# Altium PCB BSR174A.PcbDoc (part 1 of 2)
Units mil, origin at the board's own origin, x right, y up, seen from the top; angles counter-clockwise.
Board outline 4000 x 3000 mil, 6 copper layers (Top Layer, Signal Layer 1, Signal Layer 2, Signal Layer 3, Signal Layer 4, Bottom Layer), stack 61.8 mil thick; 80 components, 28 nets, 166 pads, 381 vias.
Unrouted connection lines stored in the file: 48.
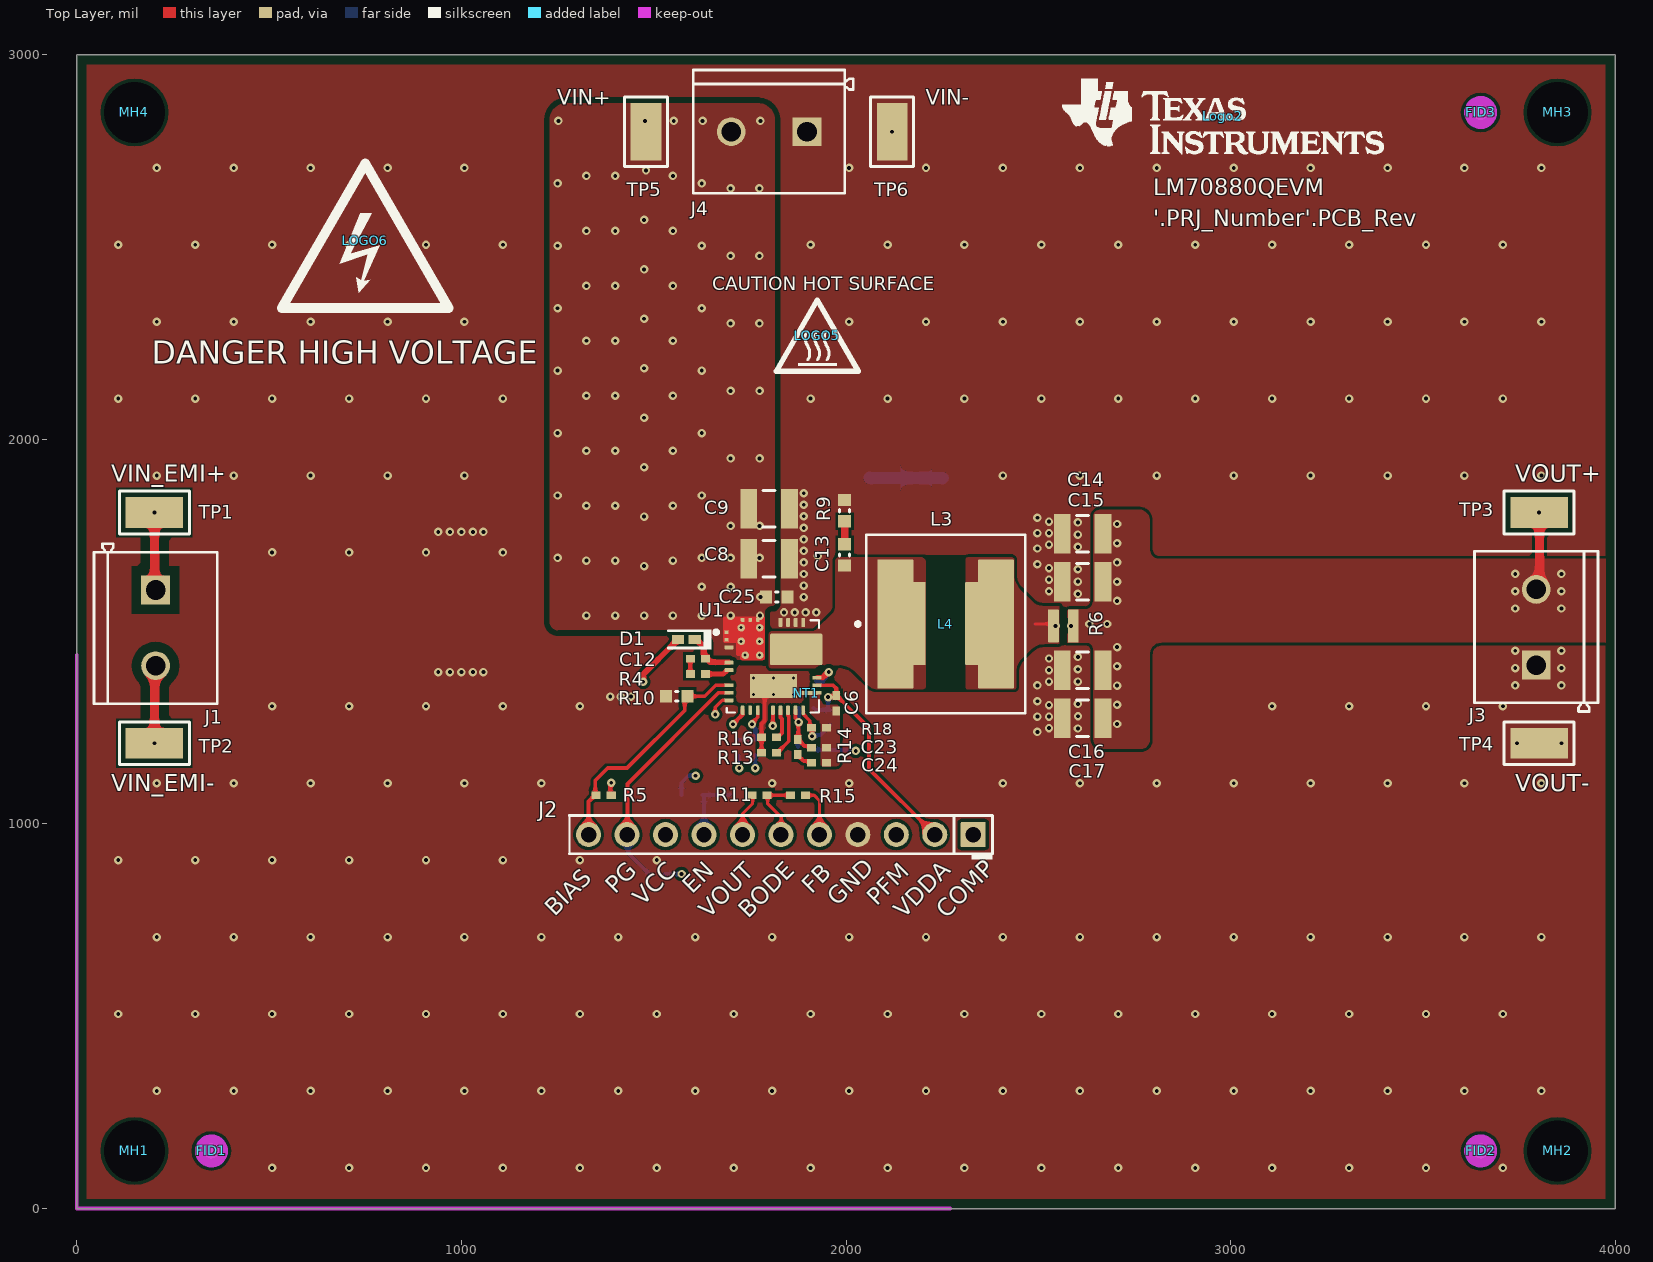
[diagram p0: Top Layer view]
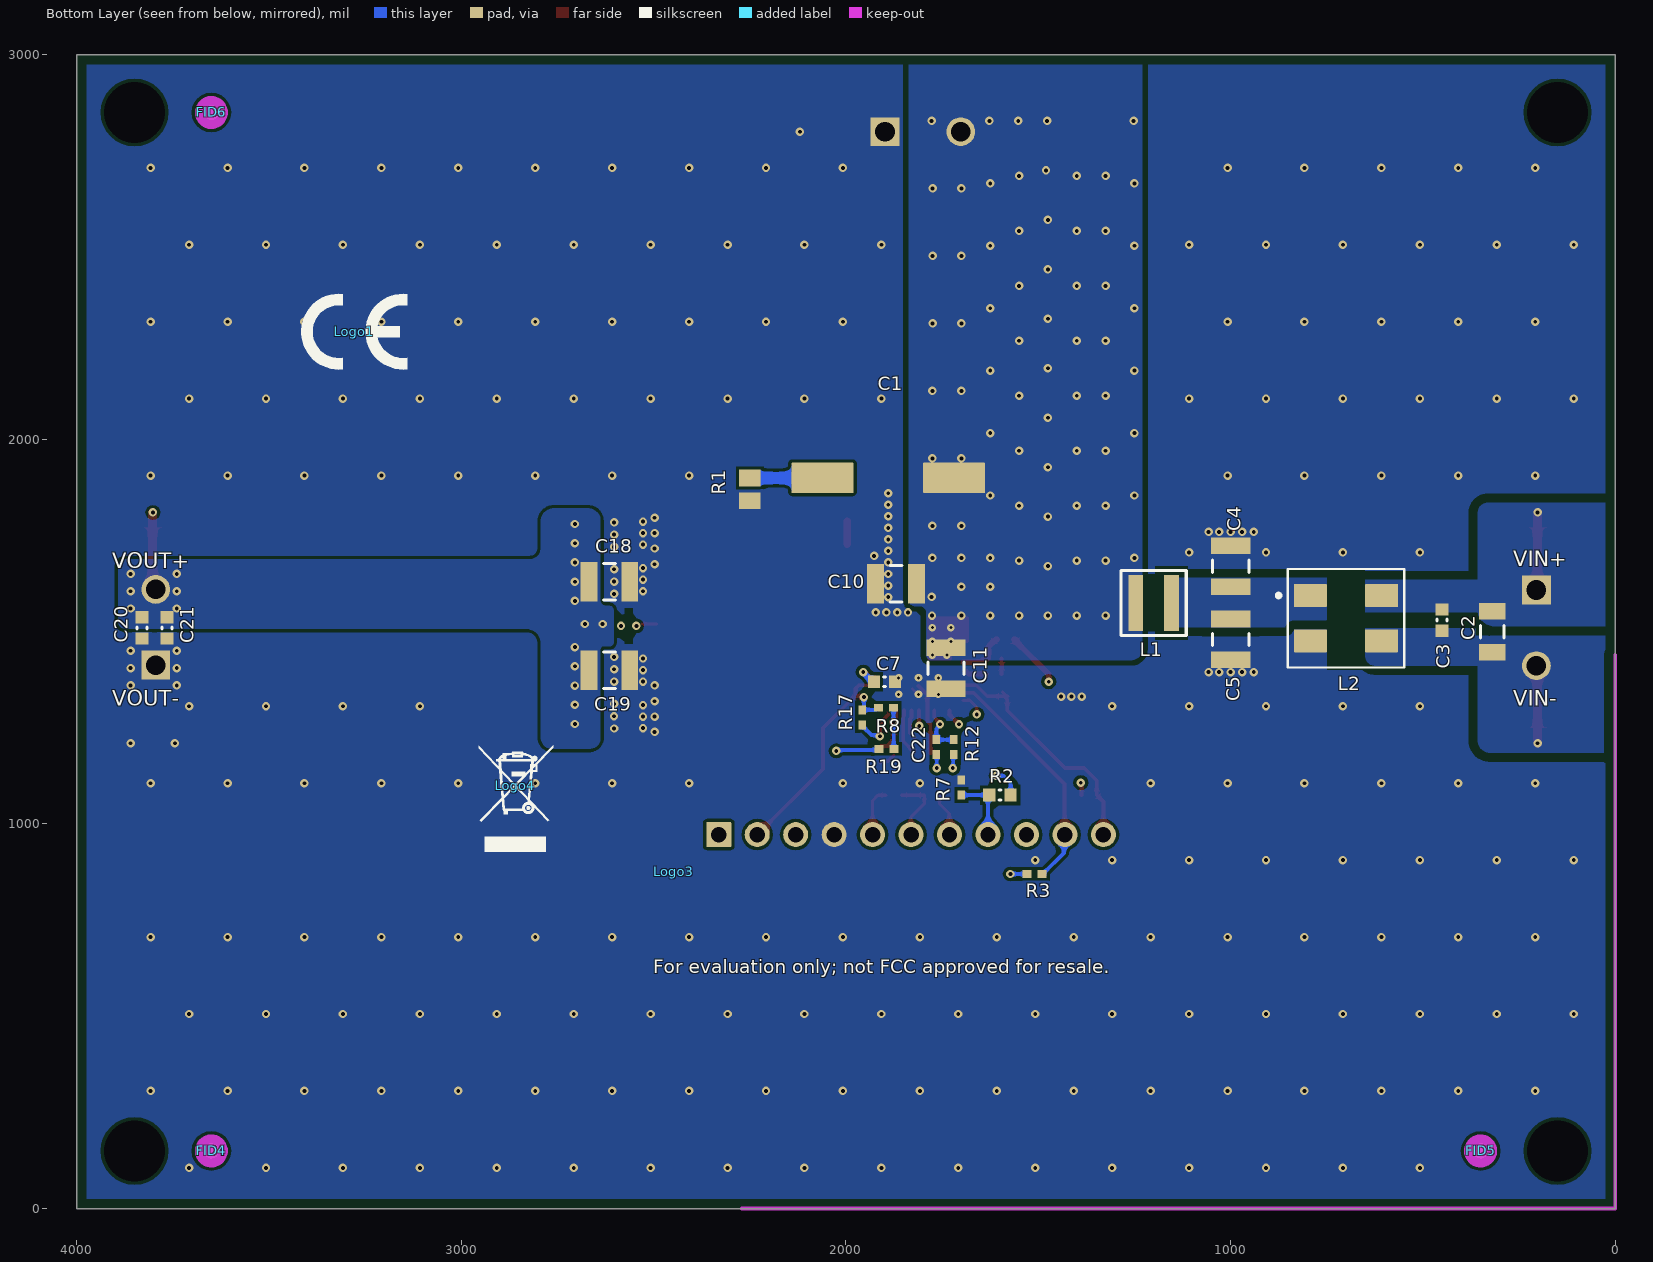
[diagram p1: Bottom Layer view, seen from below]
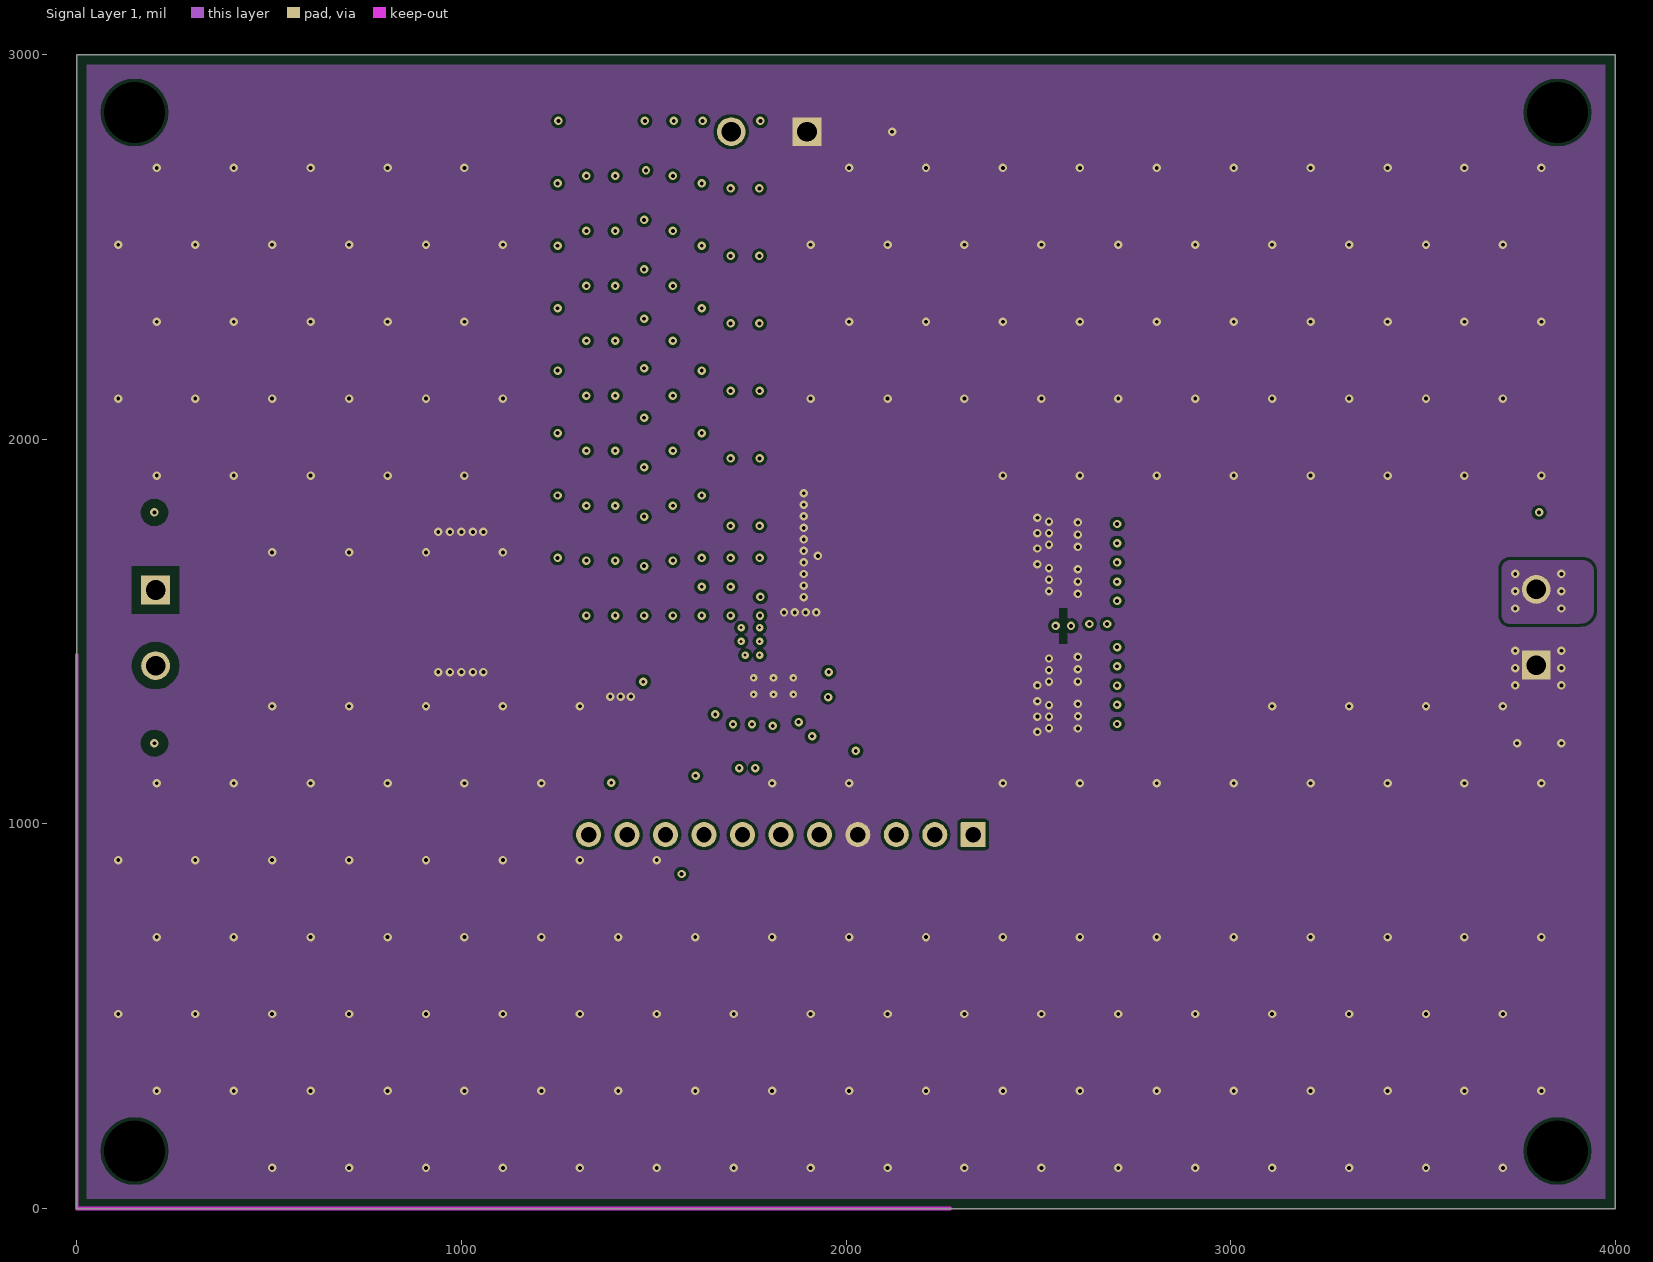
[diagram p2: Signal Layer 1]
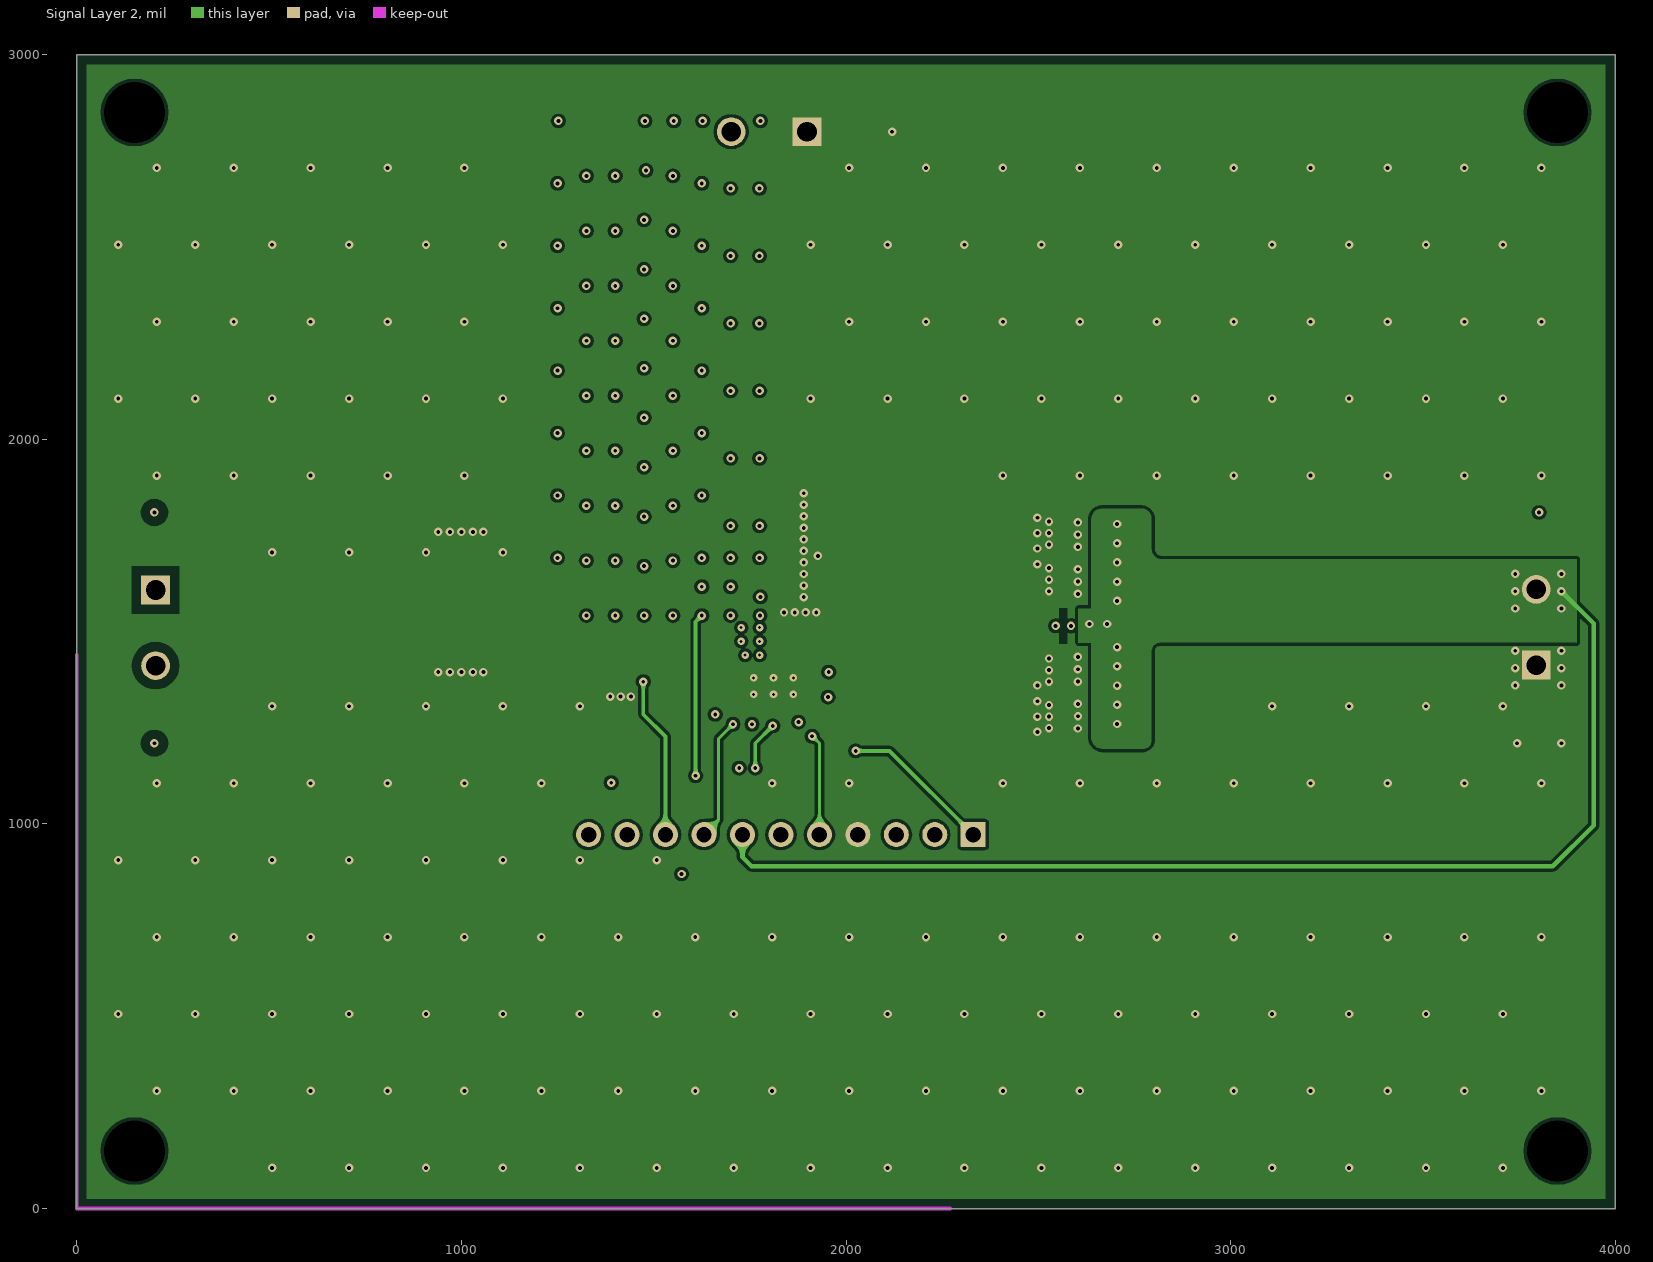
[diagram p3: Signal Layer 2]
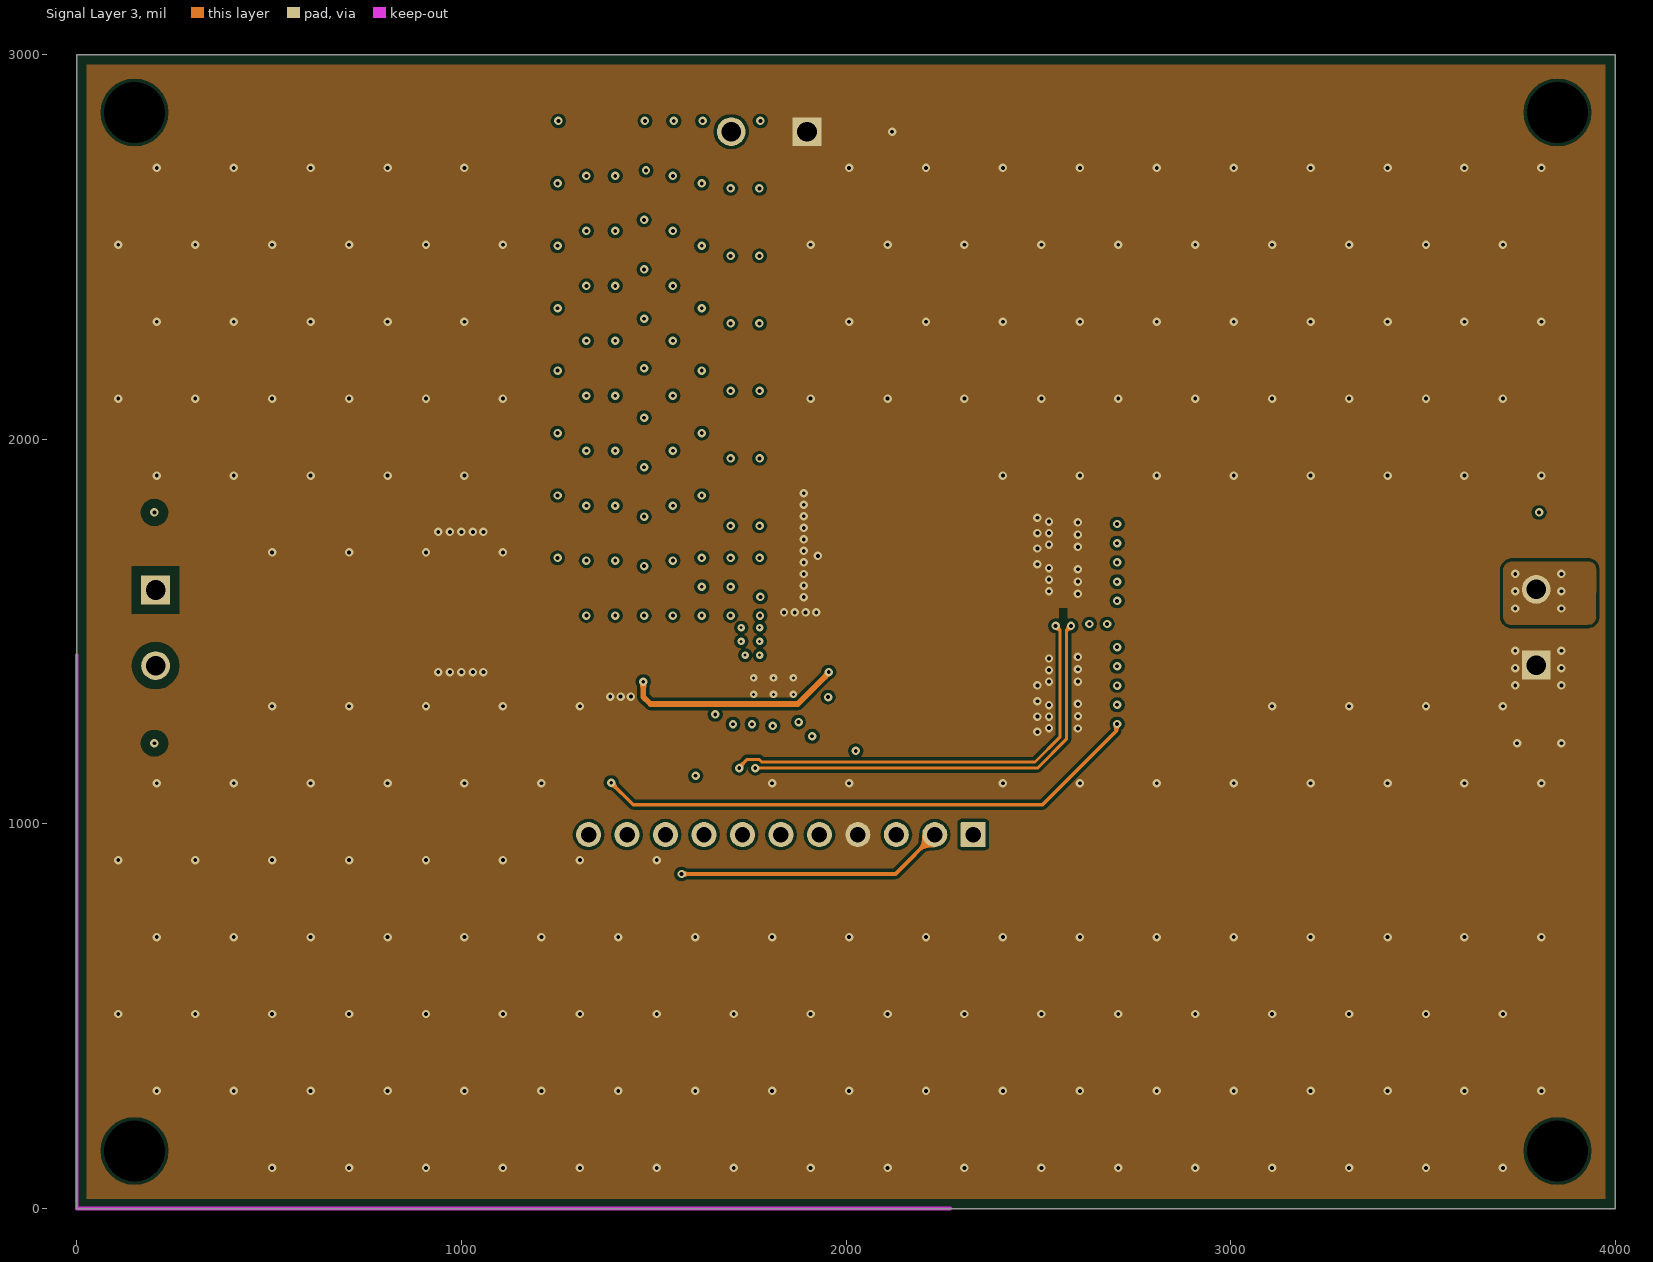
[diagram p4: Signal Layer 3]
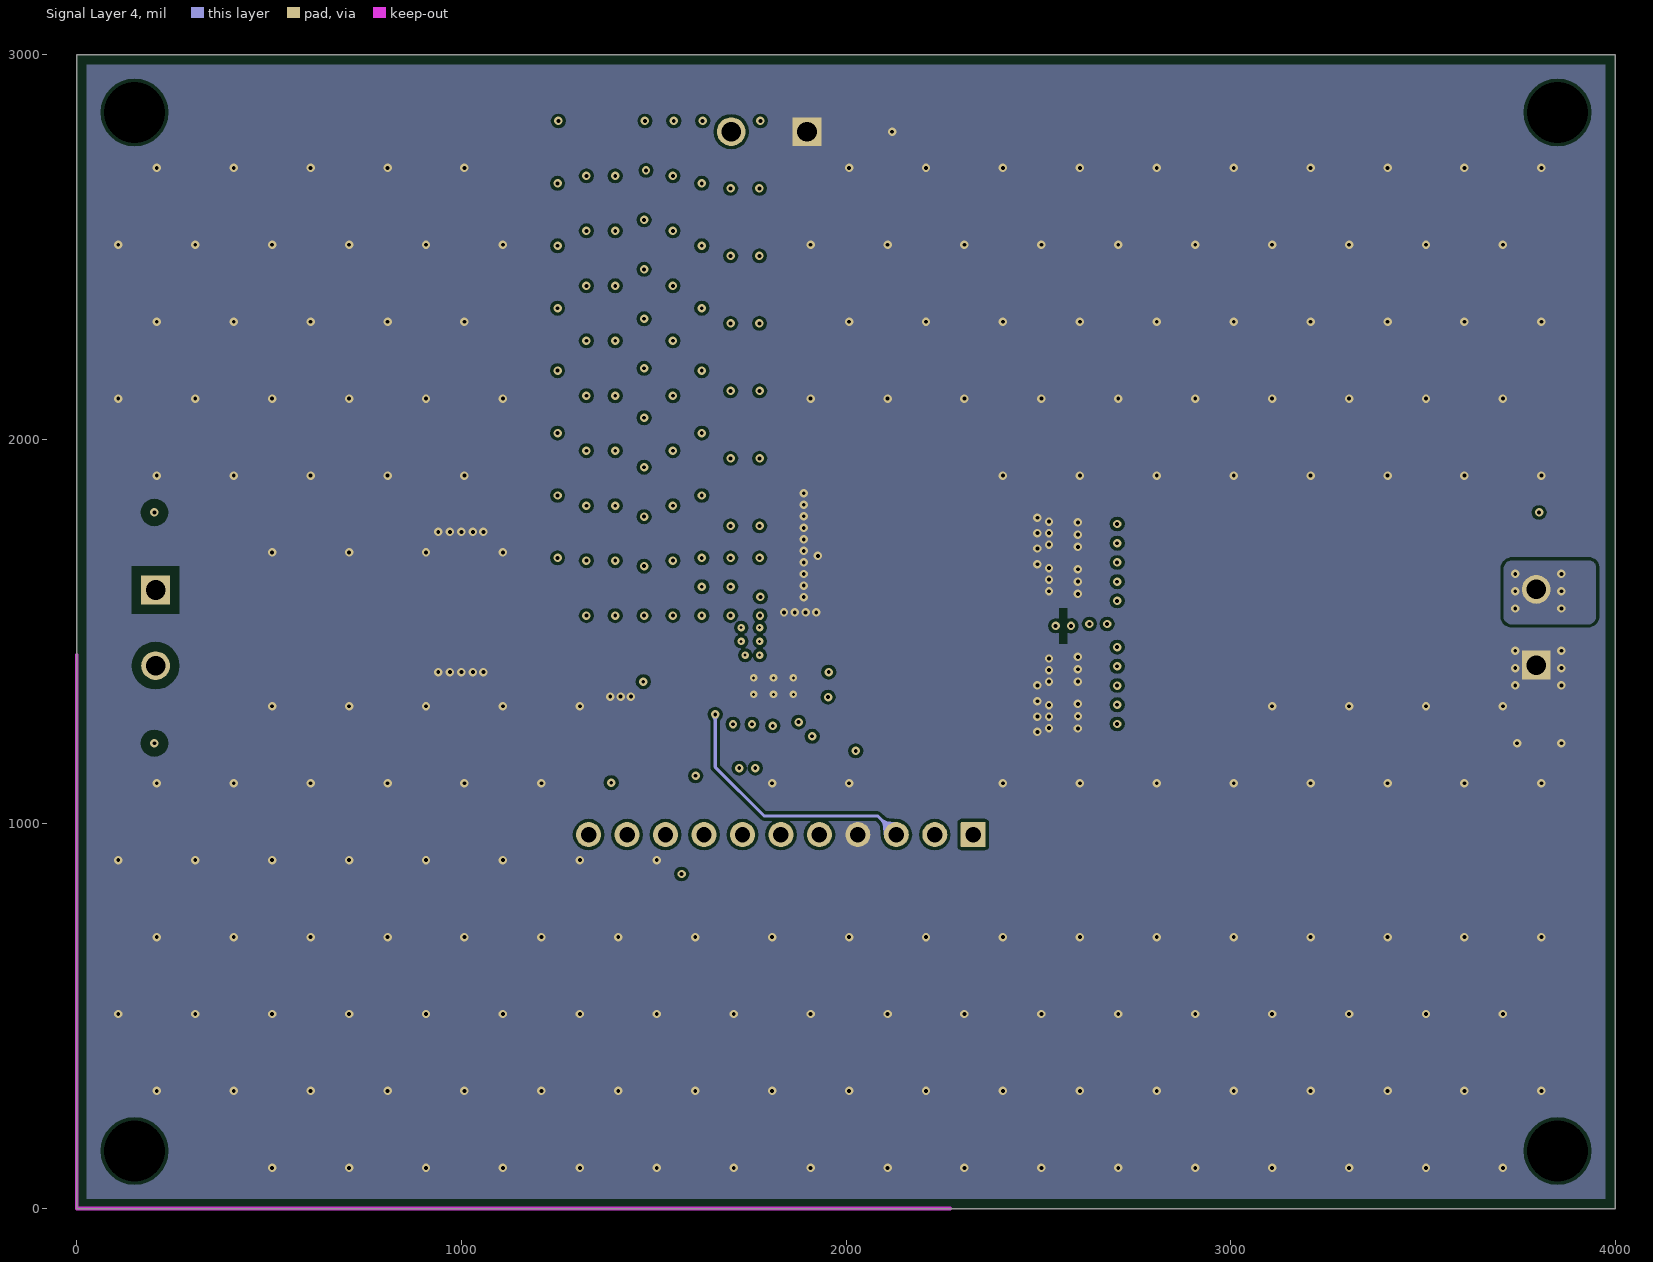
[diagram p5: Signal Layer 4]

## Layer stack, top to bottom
Top Solder: solder mask 0.4, Solder Resist, Dk 3.5
Top Layer: signal copper 2.8
Dielectric1: core 9, FR4 Hi Tg, Dk 4.8
Signal Layer 1: signal copper 2.8
Dielectric 2: prepreg 9, FR4 Hi Tg, Dk 4.2
Signal Layer 2: signal copper 2.8
Dielectric 3: core 9, FR4 Hi Tg, Dk 4.2
Signal Layer 3: signal copper 2.8
Dielectric 4: prepreg 9, FR4 Hi Tg, Dk 4.2
Signal Layer 4: signal copper 2.8
Dielectric 5: core 9, FR4 Hi Tg, Dk 4.2
Bottom Layer: signal copper 2.8
Bottom Solder: solder mask 0.4, Solder Resist, Dk 3.5

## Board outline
0,0 0,3000 4000,3000 4000,0

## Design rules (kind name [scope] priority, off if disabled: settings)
AcuteAngle [All] p1: minimum=4.50000000000000E+0001 checktracksonly=FALSE
AssemblyTestPointUsage [All] p1: valid=2
BoardOutlineClearance BoardOutlineClearance_MountingHoles [OnCopper and InComponentClass('Mounting Holes')] p1: gap=39.37 ignorepadtopadclearanceinfootprint=FALSE
BoardOutlineClearance BoardOutlineClearance_Poly [OnCopper and IsPoly] p2: gap=25 ignorepadtopadclearanceinfootprint=FALSE
BoardOutlineClearance [OnCopper and Not InComponentClass('Logo') and not InComponentClass('FiducialMark') and not InRegion(1000,500,4000,800) and not InPoly] p3: gap=50 ignorepadtopadclearanceinfootprint=FALSE
Clearance "Schematic Clearance Constraint" [InNet('NetC4_1')] p1: gap=24 ignorepadtopadclearanceinfootprint=TRUE
Clearance Clearance_5 [(InNet('NetC4_1') AND OnLayer('Bottom Layer')) vs InNet('VIN') And OnLayer('Bottom Layer')] p2: gap=15 ignorepadtopadclearanceinfootprint=FALSE
Clearance Clearance_4 [(InNet('NetC4_1') AND OnLayer('Bottom Layer')) vs InNet('GND') And OnLayer('Bottom Layer')] p3: gap=15 ignorepadtopadclearanceinfootprint=FALSE
Clearance Clearance_3 [(InNet('NetC5_1') AND OnLayer('Bottom Layer')) vs InNet('GND') And OnLayer('Bottom Layer')] p4: gap=15 ignorepadtopadclearanceinfootprint=FALSE
Clearance "SW and GND top" [(InNet('SW') AND OnLayer('Top Layer')) vs InNet('GND') And OnLayer('Top Layer')] p5: gap=8 ignorepadtopadclearanceinfootprint=FALSE
Clearance "Vin and GND top" [(InNet('VIN') AND OnLayer('Top Layer')) vs InNet('GND') And OnLayer('Top Layer')] p6: gap=15 ignorepadtopadclearanceinfootprint=FALSE
Clearance "Vin and GND layer2" [(InNet('VIN') AND OnLayer('Signal Layer 1')) vs InNet('GND') And OnLayer('Signal Layer 1')] p7: gap=8 ignorepadtopadclearanceinfootprint=FALSE
Clearance "SW to GND bottom" [(InNet('SW') AND OnLayer('Bottom Layer')) vs InNet('GND') And OnLayer('Bottom Layer')] p8: gap=8 ignorepadtopadclearanceinfootprint=FALSE
Clearance "Vin to GND bottom" [(InNet('VIN') AND OnLayer('Bottom Layer')) vs InNet('GND') And OnLayer('Bottom Layer')] p9: gap=10 ignorepadtopadclearanceinfootprint=FALSE except(15: Fill-Fill Fill-Poly Fill-Region Poly-Poly Poly-Region Region-Region)
Clearance Clearance_2 [InNamedPolygon('TOP_LAYER_SW_P2403')] p10: gap=40 ignorepadtopadclearanceinfootprint=FALSE
Clearance Clearance_1 [InNamedPolygon('TOP_LAYER_SW_P2403')] p11: gap=10 ignorepadtopadclearanceinfootprint=FALSE except(0: Arc-Hole Track-Hole SMDPad-Hole THPad-Hole Via-Hole Fill-Hole Poly-Hole Region-Hole Text-Hole)
Clearance "Schematic Clearance Constraint_2" [InNet('NetC2_1')] p12: gap=24 ignorepadtopadclearanceinfootprint=TRUE
Clearance "Schematic Clearance Constraint_1" [InNet('EMIGND')] p13: gap=24 ignorepadtopadclearanceinfootprint=FALSE
Clearance Clearance_Keepouts [((IsTrack Or IsArc) And Not InPoly) And IsFree and IsKeepOut vs ((IsTrack Or IsArc) And Not InPoly) And IsFree and IsKeepOut] p14: gap=10 ignorepadtopadclearanceinfootprint=FALSE
Clearance Clearance_VIN [(InPolygon AND InNet('GND'))] p15: gap=8 ignorepadtopadclearanceinfootprint=TRUE
Clearance Clearance_Poly [InPolygon] p16: gap=10 ignorepadtopadclearanceinfootprint=TRUE except(8: Arc-SMDPad Track-SMDPad SMDPad-SMDPad)
Clearance Clearance_FiducialMark [IsKeepOut and InComponentClass('FiducialMark') vs IsPad and InComponentClass('FiducialMark')] p17: gap=0 ignorepadtopadclearanceinfootprint=FALSE
Clearance [All] p18: gap=7.87 ignorepadtopadclearanceinfootprint=TRUE
ComponentClearance J1 [InComponent('J1') vs InComponent('C5')] p1: gap=0 collisioncheckmode=3 verticalgap=0 showdistances=FALSE
ComponentClearance J3 [InComponent('J3') vs InComponent('C33')] p2: gap=0 collisioncheckmode=3 verticalgap=0 showdistances=FALSE
ComponentClearance ComponentClearance_NetTie [(HasFootprint('Net-Tie_10mil') OR HasFootprint('Net-Tie_10milWide_30milLong'))] p3: gap=0 collisioncheckmode=3 verticalgap=0 showdistances=FALSE
ComponentClearance ComponentClearance_MountingHoles_FiducialMarks [InComponentClass('Mounting Holes') vs InComponentClass('FiducialMark')] p4: gap=50 collisioncheckmode=3 verticalgap=10 showdistances=FALSE
ComponentClearance ComponentClearance_Shunt [InComponentClass('Header') vs InComponentClass('Shunt')] p5: gap=0 collisioncheckmode=3 verticalgap=0 showdistances=FALSE
ComponentClearance ComponentClearance_Logo [InComponentClass('Logo')] p6: gap=50 collisioncheckmode=3 verticalgap=10 showdistances=FALSE
ComponentClearance ComponentClearance_ScrewToNut [(HasFootprint('NY PMS 440 0025 PH')) vs (HasFootprint('Keystone_1902C'))] p7: gap=5 collisioncheckmode=3 verticalgap=10 showdistances=FALSE
ComponentClearance ComponentClearance_MountingHoles [InComponentClass('Mounting Holes')] p8: gap=90 collisioncheckmode=3 verticalgap=100 showdistances=FALSE
ComponentClearance ComponentClearance_SmallPassives [HasFootprint('0201*') or HasFootprint('0402*') or HasFootprint('0508') or HasFootprint('0603*') or HasFootprint('0612') or HasFootprint('0805*') or HasFootprint('0815*') or HasFootprint('0830*') or HasFootprint('1206*') or HasFootprint('1210*') or HasFootprint('1808*') or HasFootprint('1812*') or HasFootprint('1825*') or HasFootprint('2010*') or HasFootprint('2220*') or HasFootprint('2225*') or HasFootprint('2512*') or HasFootprint('2728*') or HasFootprint('3518*') vs HasFootprint('0201*') or HasFootprint('0402*') or HasFootprint('0508') or HasFootprint('0603*') or HasFootprint('0612') or HasFootprint('0805*') or HasFootprint('0815*') or HasFootprint('0830*') or HasFootprint('1206*') or HasFootprint('1210*') or HasFootprint('1808*') or HasFootprint('1812*') or HasFootprint('1825*') or HasFootprint('2010*') or HasFootprint('2220*') or HasFootprint('2225*') or HasFootprint('2512*') or HasFootprint('2728*') or HasFootprint('3518*')] p9: gap=14.96 collisioncheckmode=3 verticalgap=10 showdistances=FALSE
ComponentClearance ComponentClearance_THtoSMT [IsThruComponent vs IsSMTComponent] p10: gap=40 collisioncheckmode=3 verticalgap=30 showdistances=FALSE
ComponentClearance ComponentClearance_THtoTH [IsThruComponent vs IsThruComponent] p11: gap=30 collisioncheckmode=3 verticalgap=30 showdistances=FALSE
ComponentClearance "Clearance L3" [InComponent('L4') vs InComponent('L3')] p12: gap=0 collisioncheckmode=3 verticalgap=0 showdistances=FALSE
ComponentClearance [All] p13: gap=15 collisioncheckmode=3 verticalgap=2 showdistances=FALSE
DiffPairsRouting [All] p1: maxlimit=100 minlimit=10 mostfreqgap=10 toplayer_minwidth=15 toplayer_maxwidth=15 toplayer_prefwidth=15 midlayer1_minwidth=15 midlayer1_maxwidth=15 midlayer1_prefwidth=15 midlayer2_minwidth=15 midlayer2_maxwidth=15 midlayer2_prefwidth=15 midlayer3_minwidth=15 midlayer3_maxwidth=15 midlayer3_prefwidth=15 midlayer4_minwidth=15 midlayer4_maxwidth=15 midlayer4_prefwidth=15 bottomlayer_minwidth=15 bottomlayer_maxwidth=15 bottomlayer_prefwidth=15 maxuncoupledlength=1000
FabricationTestPointUsage TestPointUsage [All] p1: valid=2 allowmultiple=FALSE
FabricationTestpoint Testpoint [All] p1: side=3 testpointundercomponent=TRUE minsize=40 maxsize=100 preferedsize=60 minholesize=0 maxholesize=40 preferedholesize=32 testpointgrid=1 allowsidetop=TRUE allowsidebottom=TRUE usegrid=TRUE gridtolerance=0.01
FanoutControl Fanout_LCC [IsLCC] p1: bgadir=Out bgaviamode=Centered fanoutstyle=Auto fanoutdirection=Alternating viagrid=1 // Fanout_LCC (Default Rule)
FanoutControl Fanout_BGA [IsBGA] p2: bgadir=Out bgaviamode=Centered fanoutstyle=Auto fanoutdirection=Alternating viagrid=1 // Fanout_BGA (Default Rule)
FanoutControl Fanout_Default [All] p4: bgadir=Out bgaviamode=Centered fanoutstyle=Auto fanoutdirection=Alternating viagrid=1 // Fanout_Default (Default Rule)
FanoutControl Fanout_Small [(CompPinCount < 5)] p5: bgadir=Out bgaviamode=Centered fanoutstyle=Auto fanoutdirection=OutThenIn viagrid=1 // Fanout_Small (Default Rule)
HoleSize [All] p1: absolutevalues=TRUE maxlimit=251 minlimit=7.87 maxpercent=80.000 minpercent=20.000
MinimumAnnularRing MinimumAnnularRing_ThermalPadVias [IsVia and InAnyComponent] p1: minimumring=5.91
MinimumAnnularRing [All] p2: minimumring=5
MinimumSolderMaskSliver MinimumSolderMaskSliver_Logo [InComponentClass('Logo') vs InComponentClass('Logo')] p1: minsoldermaskwidth=0.7
MinimumSolderMaskSliver [All] p2: minsoldermaskwidth=3.94
PlaneClearance PlaneClearance_1 [InNet('GND') And OnLayer('Signal Layer 1')] p1: clearance=8
PlaneClearance [All] p2: clearance=20
PlaneConnect [All] p1: planeconnectstyle=Relief reliefexpansion=10 reliefentries=4 reliefconductorwidth=10 reliefairgap=10
PolygonConnect [All] p1: connectstyle=Direct reliefconductorwidth=10 reliefentries=4 polygonreliefangle="90 Angle" airgapwidth=10
RoutingVias ThermalPadVias [IsVia and InAnyComponent] p1: holewidth=7.87 width=19.68 viastyle="Through Hole" minholewidth=7.87 minwidth=19.68 maxholewidth=12.99 maxwidth=23.62
RoutingVias [All] p2: holewidth=10 width=22 viastyle="Through Hole" minholewidth=7.87 minwidth=18 maxholewidth=40 maxwidth=65
SilkToBoardRegionClearance [Not ((IsComment or IsDesignator) And (Hide <> 'False')) and not InRegion(1000,500,4000,800)] p1:
SilkToSilkClearance SilkToSilkClearance_Pb-FreeLogo [(HasFootprint('Pb-Free_Overlay_Medium') OR HasFootprint('Pb-Free_Overlay_Small')) vs (HasFootprint('Pb-Free_Overlay_Medium') OR HasFootprint('Pb-Free_Overlay_Small'))] p1: silktosilkclearance=0
SilkToSilkClearance [All] p2: silktosilkclearance=3.94
SilkToSolderMaskClearance SilkToComponentPadClearance [(IsPad or IsFill or IsRegion) and InAnycomponent] p1: minsilkscreentomaskgap=5 clearancetoexposedcopper=TRUE
SilkToSolderMaskClearance "Silk to Solder Mask Opening" [All] p2: minsilkscreentomaskgap=3.94 clearancetoexposedcopper=FALSE
SolderMaskExpansion [All] p1: expansion=1.97 istentingtop=FALSE
UnRoutedNet [All] p1: checkbadconnections=TRUE
Width [All] p1: maxlimit=250 minlimit=8 preferedwidth=10 checkconnectedcopper=TRUE
13 further rules are at their usual default settings.

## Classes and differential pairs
component class BSR174A-Main: C1 C2 C3 C4 C5 C6 C7 C8 C9 C10 C11 C12 C13 C14 C15 C16 C17 C18 C19 C20 C21 C22 C23 C24 C25 D1 J1 J2 J3 J4 L1 L2 L3 L4 NT1 R1 R2 R3 R4 R5 R6 R7 R8 R9 R10 R11 R12 R13 R14 R15 R16 R17 R18 R19 RDC TP1 TP2 TP3 TP4 TP5 TP6 U1
component class Header: J2
component class Logo: Logo2
component class BSR174A-Hardware: FID1 FID2 FID3 FID4 FID5 FID6 H10 Logo1 Logo2 Logo3 Logo4 LOGO5 LOGO6 MH1 MH2 MH3 MH4 ZZ1 ZZ2 ZZ3
component class FiducialMark: FID1 FID2 FID3 FID4 FID5 FID6
component class AssemblyNote: ZZ1 ZZ2 ZZ3

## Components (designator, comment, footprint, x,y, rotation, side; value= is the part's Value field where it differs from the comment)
C1 "EEE-TG2A330P" TG_V_1000x1020 1890,1900 r0 bottom value=33uF
C2 "CGA5L3X7S2A225K160AB" 1206_180L 320,1500 r270 bottom value=2.2uF
C3 "GCJ188R72A104KA01D" 0603L 450,1530 r270 bottom value=0.1uF
C4 "GCM32DC72A475KE02L" 1210_220L 1000,1670 r90 bottom value=4.7uF
C5 "GCM32DC72A475KE02L" 1210_220L 1000,1480 r270 bottom value=4.7uF
C6 "C0402C104K8RACAUTO" 0402L 1975,1314 r90 top value=0.1uF
C7 "GRM188Z71A475ME15D" 0603L 1900,1370 r180 bottom value=4.7uF
C8 "GCM32DC72A475KE02L" 1210_220L 1800,1690 r0 top value=4.7uF
C9 "GCM32DC72A475KE02L" 1210_220L 1800,1820 r0 top value=4.7uF
C10 "GCM32DC72A475KE02L" 1210_220L 1870,1625 r0 bottom value=4.7uF
C11 "GCM32DC72A475KE02L" 1210_220L 1740,1405 r270 bottom value=4.7uF
C12 "GRM155R71E473KA88D" 0402L 1615,1430 r180 top value=0.047uF
C13 "GRM1885C2A101JA01D" 0603L 1996.45,1699.65 r90 top value=100pF
C14 "GRM32ER71A476KE15L" 1210_270L 2615,1755 r180 top value=47uF
C15 "GRM32ER71A476KE15L" 1210_270L 2615,1630 r180 top value=47uF
C16 "GRM32ER71A476KE15L" 1210_270L 2615,1400 r180 top value=47uF
C17 "GRM32ER71A476KE15L" 1210_270L 2615,1275 r180 top value=47uF
C18 "GRM32ER71A476KE15L" 1210_270L 2615,1630 r180 bottom value=47uF
C19 "GRM32ER71A476KE15L" 1210_270L 2615,1400 r180 bottom value=47uF
C20 "CGA3E2X7R1H104K080AA" 0603L 3830,1510 r270 bottom value=0.1uF
C21 "CGA3E2X7R1H104K080AA" 0603L 3765,1510 r270 bottom value=0.1uF
C22 "GCM1555C1H330JA16D" 0402L 1765,1200 r90 bottom value=33pF
C23 "CGA2B2C0G1H470J050BA" 0402L 1930,1198 r0 top value=47pF
C24 "CGA2B2X7R1H682K050BA" 0402L 1930,1159 r0 top value=6800pF
C25 "GCJ188R72A104KA01D" 0603L 1820,1590 r0 top value=0.1uF
D1 "BAT41KFILM" SOD-523 1585,1480 r180 top value=100V
FID1 "Fiducial" Fiducial10-20 350,150 r0 top
FID2 "Fiducial" Fiducial10-20 3650,150 r0 top
FID3 "Fiducial" Fiducial10-20 3650,2850 r0 top
FID4 "Fiducial" Fiducial10-20 3650,150 r90 bottom
FID5 "Fiducial" Fiducial10-20 350,150 r90 bottom
FID6 "Fiducial" Fiducial10-20 3650,2850 r90 bottom
J1 "Header_2x1" Phoenix_1729018 205,1510 r270 top
J2 "TSW-111-07-G-S" TSW-111-07-G-S 1830.81,972.34 r180 top
J3 "Header_2x1" Phoenix_1729018 3794.59,1511.57 r90 top
J4 "1729018" Phoenix_1729018 1800,2800 r180 top
L1 "74438356010" WE-MAPI_4020 1200,1575 r0 bottom value=1uH
L2 "CM7060P701R-10" FP-CM7060P701R-10_SMT_CMC_7MM0_6MM0-MFG 700,1535 r180 bottom
L3 "XGL6060-332MEC" FP-XGL6060-332MEC_SMT_6MM51_6MM71-MFG 2258.47,1521.46 r0 top value=3.3uH
L4 "XGL1060-332MEC" FP-XGL1060-332MEC_SMT2_10MM0_11MM3-MFG 2259.09,1519.94 r0 top value=3.3uH
Logo1 "CE Mark" CE_Mark_5mm 3278.8,2280 r180 bottom
Logo2 "Texas Instruments" TI_Stacked_Overlay_Small 2980,2840 r0 top
Logo3 "FCC disclaimer" FCC_disclaimer 2447.81,875.34 r180 bottom
Logo4 "WEEE logo" WEEE_Minimum 2860,1100 r180 bottom
LOGO5 "CAUTION HOT SURFACE" IEC_HotSurface_Small 1925.37,2270.02 r0 top
LOGO6 "DANGER HIGH VOLTAGE" IEC_HighVoltage_Medium 750,2517.01 r0 top
MH1 "MTG_NoPads" MTG_159mil 150,150 r0 top
MH2 "MTG_NoPads" MTG_159mil 3850,150 r0 top
MH3 "MTG_NoPads" MTG_159mil 3850,2850 r0 top
MH4 "MTG_NoPads" MTG_159mil 150,2850 r0 top
NT1 "Net-Tie" Net-Tie_10milWide_30milLong 1896.25,1340.32 r0 top net-tie
R1 "ERJ-6GEY0R00V" 0805L 2250,1870 r90 bottom value=0
R2 "CRCW0603100KFKEA" 0603L 1600,1075 r180 bottom value=100k
R3 "RMCF0402FT100K" 0402L 1510,870 r0 bottom value=100k
R4 "CRCW04020000Z0EDHP" 0402L 1615,1390 r180 top value=0
R5 "CRCW04020000Z0EDHP" 0402L 1370,1075 r180 top value=0
R6 "KRL2012E-M-R005-F-T5" FP-KRL2012E-M-R005-F-T5_0805_WIDE-MFG 2565,1515 r0 top value=5m
R7 "CRCW040219K1FKED" 0402L 1700,1095 r270 bottom value=19.1k
R8 "RMCF0402FT100K" 0402L 1896.26,1301.73 r0 bottom value=100k
R9 "CRCW06032R00FKEA" 0603L 1996.45,1814.68 r90 top value=2.00
R10 "CRCW06030000Z0EA" 0603L 1560,1332.13 r0 top value=0
R11 "CRCW040249R9FKED" 0402L 1775,1075 r180 top value=49.9
R12 "CRCW040249R9FKED" 0402L 1720,1200 r270 bottom value=49.9
R13 "CRCW040254K9FKED" 0402L 1800,1185 r180 top value=54.9k
R14 "CRCW04025K76FKED" 0402L 1875,1200 r90 top value=5.76k
R15 "CRCW0402100KFKED" 0402L 1875,1075 r180 top value=100k
R16 "CRCW040230K1FKED" 0402L 1800,1225 r0 top value=30.1k
R17 "CRCW040224K9FKED" 0402L 1958.21,1276.97 r90 bottom value=24.9k
R18 "CRCW040219K6FKED" 0402L 1930,1250 r180 top value=19.6k
R19 "CRCW04020000Z0ED" 0402L 1895,1195 r180 bottom value=0
TP1 "5019" Keystone_5019 202,1810 r0 top
TP2 "5019" Keystone_5019 202,1210 r0 top
TP3 "5019" Keystone_5019 3802,1810 r0 top
TP4 "5019" Keystone_5019 3802,1210 r0 top
TP5 "5019" Keystone_5019 1480,2800 r90 top
TP6 "5019" Keystone_5019 2120,2800 r90 top
U1 "LM70880RRXRQ1" RRX0029B-MFG 1810,1410 r0 top
ZZ1 "These assemblies are ESD sensitive, ESD precautions shall be observed." AssemblyNote 142,3585.11 r0 top
ZZ2 "These assemblies must be clean and free from flux and all contaminants. Use of no clean flux is not acceptable." AssemblyNote 142,3496.56 r0 top
ZZ3 "These assemblies must comply with workmanship standards IPC-A-610 Class 2, unless otherwise specified." AssemblyNote 142,3408 r0 top

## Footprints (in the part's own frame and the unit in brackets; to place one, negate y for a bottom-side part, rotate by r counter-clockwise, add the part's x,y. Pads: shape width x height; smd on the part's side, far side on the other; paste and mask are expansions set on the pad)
0402L [mm] "0402 from SM-752 data"
  rect 0.6x0.5 smd: 1(-0.5,0) 2(0.5,0)
  body extent -0.55,-0.3 0.55,0.3, height 0.6
0603L [mm] "0603 from SM-752 data"
  rect 0.8x0.85 smd: 1(-0.7,0) 2(0.7,0)
  silkscreen extent -0.07,-0.33 0.07,0.33, body extent -0.87,-0.47 0.87,0.47, height 1
0805L [mm] "0805 from SM-752 data"
  rect 1.1x1.4 smd: 1(-0.75,0) 2(0.75,0)
  body extent -1.1,-0.72 1.1,0.72, height 1.45
1206_180L [mm] "1206_180"
  rect 1.1x1.75 smd: 1(-1.35,0) 2(1.35,0)
  silkscreen extent -0.4,-0.77 0.4,0.77, body extent -1.75,-0.95 1.75,0.95, height 1.8
1210_220L [mm] "1210"
  rect 1.1x2.6 smd: 1(-1.35,0) 2(1.35,0)
  silkscreen extent -0.4,-1.2 0.4,1.2, body extent -1.7,-1.35 1.7,1.35, height 2.2
1210_270L [mm] "1210"
  rect 1.1x2.6 smd: 1(-1.35,0) 2(1.35,0)
  silkscreen extent -0.4,-1.2 0.4,1.2, body extent -1.7,-1.35 1.7,1.35, height 2.7
AssemblyNote [mil] "Assembly Note"
CE_Mark_5mm [mil] "Minimum text height for CE Mark"
  silkscreen extent -138,-98 138,98
FCC_disclaimer [mil]
Fiducial10-20 [mm]
  round 1 smd mask+0.5: 1(0,0)
  Top Layer keep-out circle w1.178: c0,0 r0.5
FP-CM7060P701R-10_SMT_CMC_7MM0_6MM0-MFG [mm]
  rrect7% 2.2x1.5 smd paste+0 mask+0: 1(-2.35,1.5) 2(-2.35,-1.5) 3(2.35,-1.5) 4(2.35,1.5)
  silkscreen extent -4.58,-3.25 3.85,3.25, body extent -3.5,-3 3.5,3, height 3.8
FP-KRL2012E-M-R005-F-T5_0805_WIDE-MFG [mm]
  rrect14% 0.7x2.2 smd paste+0 mask+0: 1(-0.65,0) 2(0.65,0)
  body extent -1.1,-1.2 1.1,1.2, height 0.25
FP-XGL1060-332MEC_SMT2_10MM0_11MM3-MFG [mm]
  rrect4% 2.38x8.5 smd paste+0 mask+0: 1(-3.325,0) 2(3.325,0)
  silkscreen extent -5.92,-5.9 5.25,5.9, body extent -5.35,-6 5.35,6, height 0.25
FP-XGL6060-332MEC_SMT_6MM51_6MM71-MFG [mm]
  rrect7% 1.43x5.5 smd paste+0 mask+0: 1(-2.02,0) 2(2.02,0)
  body extent -3.45,-3.55 3.45,3.55, height 0.25
IEC_HighVoltage_Medium [mil]
  silkscreen extent -217,-176 217,200
IEC_HotSurface_Small [mil]
  silkscreen extent -107,-93 107,92
Keystone_5019 [mm] "Test Point, Miniature, SMT"
  rect 3.8x2.03 smd: 1(0,0)
  silkscreen extent -2.31,-1.42 2.31,1.42, body extent -1.9,-1.02 1.9,1.02, height 2.29
MTG_159mil [mil] "159mil Non Plated Hole"
  round 150 hole 159 unplated: 1(0,0)
Net-Tie_10milWide_30milLong [mil] "10mil net tie, no solder mask opening, no solder paste"
  rect 30x10 smd paste-5 mask-5: 1(-15,0) 2(15,0)
Phoenix_1729018 [mm] "Phoenix Contact"
  rect 1.905x1.905 hole 1.3: 1(-2.5,0)
  round 1.9 hole 1.3: 2(2.5,0)
  silkscreen extent -5.56,-4.08 5.01,4.07, body extent -5.56,-4.08 5.01,4.07, height 10
RRX0029B-MFG [mm]
  rrect40% 0.267x0.25 smd paste+0 mask-1000: 1(-3.066,2.25) 2(-3.066,1.75)
  rrect40% 0.6x0.25 smd paste+0 mask+0: 3(-2.9,1.25) 4(-2.9,0.25) 5(-2.9,-0.25) 6(-2.9,-1.25) 7(-2.9,-1.75) 8(-2.9,-2.25) 17(2.9,-1.75) 18(2.9,-1.25) 19(2.9,-0.75)
  rrect40% 0.25x0.6 smd paste+0 mask+0: 9(-2,-2.9) 10(-1.5,-2.9) 11(-1,-2.9) 12(0,-2.9) 13(0.5,-2.9) 14(1,-2.9) 15(1.5,-2.9) 16(2,-2.9) 23(2,2.9) 24(1.5,2.9) 25(1,2.9) 26(0.5,2.9)
  rrect40% 0.293x0.25 smd paste+0 mask-1000: 20(3.054,0.75) 21(3.054,1.25) 22(3.054,1.75)
  rrect40% 0.25x0.258 smd paste+0 mask-1000: 27(-1,3.071) 28(-1.5,3.071) 29(-2,3.071)
  rrect6% 3.125x1.584 smd paste-1000 mask+0: 30(0.037,-1.308)
  rrect11% 3.465x2.1 smd paste-1000 mask-1000: ""(1.537,1.12)
  Top Layer region: -3.27,3.22 -3.263,3.245 -3.245,3.263 -3.22,3.27 -3.22,3.27 -0.605,3.27 -0.586,3.266 -0.57,3.255 -0.559,3.239 -0.555,3.22 -0.555,3.22 -0.555,0.534 -0.564,0.488 -0.59,0.449 -0.629,0.423 -0.675,0.414 -0.675,0.414 -2.034,0.414 -2.08,0.423 -2.119,0.449 -2.145,0.488 -2.154,0.534 -2.154,0.534 -2.154,0.641 -2.158,0.66 -2.169,0.676 -2.185,0.687 -2.204,0.691 -2.204,0.691 -2.3,0.691 -2.346,0.7 -2.385,0.726 -2.411,0.765 -2.42,0.811 -2.42,0.811 -2.42,1.505 -2.427,1.53 -2.445,1.548 -2.47,1.555 -2.47,1.555 -3.15,1.555 -3.196,1.564 -3.235,1.59 -3.261,1.629 -3.27,1.675 -3.27,1.675
  silkscreen extent -3.87,-3.05 3.05,3.05, body extent -3.37,-3.3 3.37,3.37, height 0.25
SOD-523 [mm] "NXP Semiconductor recommended land pattern, nominal STEP model"
  rect 0.8x0.6 smd paste-0.05: 1(-0.55,0) 2(0.55,0)
  silkscreen extent -1.65,-0.66 1.2,0.66, body extent -0.8,-0.4 0.8,0.4, height 0.72
TG_V_1000x1020 [mm] "SMD, 2-Leads, 10 mm Dia, Pin Spacing 8.7 mm"
  rrect5% 4.1x2 smd: 1(-4.35,0) 2(4.35,0)
  body extent -5.8,-5.15 5.8,5.15, height 10.5
TI_Stacked_Overlay_Small [mil]
  silkscreen extent -418,-98 418,98
TSW-111-07-G-S [mm] "Samtec 100mil, 1x11, 230 mil above insulator"
  rrect6% 1.65x1.65 hole 1.016: 1(-12.7,0)
  round 1.65 hole 1.016: 2(-10.16,0) 3(-7.62,0) 4(-5.08,0) 5(-2.54,0) 6(0,0) 7(2.54,0) 8(5.08,0) 9(7.62,0) 10(10.16,0) 11(12.7,0)
  silkscreen extent -13.97,-1.27 13.97,1.65, body extent -13.97,-1.27 13.97,1.27, height 8.38
WE-MAPI_4020 [mm] "SMD, 2-Leads, Body 4.1x4.1mm"
  rect 0.98x3.7 smd: 1(-1.185,0) 2(1.185,0)
  silkscreen extent -2.15,-2.15 2.15,2.15, body extent -2.15,-2.15 2.15,2.15, height 2.1
WEEE_Minimum [mil] "WEEElie bin"
  silkscreen extent -95,-172 99,104

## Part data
C1: library part CMP-0086185-1, "CAP, AL, 33 µF, 100 V, +/- 20%, 1 ohm, AEC-Q200 Grade 1, SMD", Cap_Case=10x10.2mm, Manufacturer=Panasonic, Tolerance_%=20%, Value1="1 ohm", Value2=100V, ValueDisplayed=33µF
C2: library part CMP-0008790-2, "CAP, CERM, 2.2 uF, 100 V, +/- 10%, X7S, AEC-Q200 Grade 1, 1206", Cap_Case=1206_180, Manufacturer=TDK, Supplier Part Number 1=445-6994-1-ND, TempCo=X7S, Tolerance_%=10%, Value1="0.005718 ohm", Value2=100V, ValueDisplayed=2.2uF
C3 C25: library part CMP-0064935-4, "CAP, CERM, 0.1 uF, 100 V,+/- 10%, X7R, AEC-Q200 Grade 1, 0603", Cap_Case=0603, Manufacturer=MuRata, Supplier Part Number 1=490-13420-1-ND, TempCo=X7R, Tolerance_%=10%, Value1=Unknown, Value2=100V, ValueDisplayed=0.1uF
C4 C5 C8 C9 C10 C11: library part CMP-0082268-1, "CAP, CERM, 4.7 µF, 100 V,+/- 10%, X7S, AEC-Q200 Grade 1, 1210", Cap_Case=1210, Manufacturer=MuRata, Supplier Part Number 1=490-14484-1-ND, TempCo=X7S, Tolerance_%=10%, Value1="0.001 ohm", Value2=100V, ValueDisplayed=4.7µF
C6: library part CMP-0079150-1, "CAP, CERM, 0.1 µF, 10 V,+/- 10%, X7R, AEC-Q200 Grade 1, 0402", Cap_Case=0402, Manufacturer=Kemet, Supplier Part Number 1=399-15984-1-ND, TempCo=X7R, Tolerance_%=10%, Value2=10V, ValueDisplayed=0.1µF
C7: library part CMP-0007498-4, "CAP, CERM, 4.7 uF, 10 V, +/- 20%, X7R, 0603", Cap_Case=0603, Manufacturer=MuRata, TempCo=X7R, Tolerance_%=20%, Value1=Unknown, Value2=10V, ValueDisplayed=4.7uF
C12: library part CMP-0006669-2, "CAP, CERM, 0.047 uF, 25 V, +/- 10%, X7R, 0402", Cap_Case=0402, Manufacturer=MuRata, Supplier Part Number 1=490-3254-1-ND, TempCo=X7R, Tolerance_%=10%, Value1=Unknown, Value2=25V, ValueDisplayed=0.047uF
C13: library part CMP-0007237-4, "CAP, CERM, 100 pF, 100 V, +/- 5%, C0G/NP0, 0603", Cap_Case=0603, Manufacturer=MuRata, Supplier Part Number 1=490-1351-1-ND, TempCo=C0G/NP0, Tolerance_%=5%, Value1=Unknown, Value2=100V, ValueDisplayed=100pF
C14 C15 C16 C17 C18 C19: library part CMP-0009220-2, "CAP, CERM, 47 uF, 10 V, +/- 10%, X7R, 1210", Cap_Case=1210, Manufacturer=MuRata, Supplier Part Number 1=490-5312-1-ND, TempCo=X7R, Tolerance_%=10%, Value1=Unknown, Value2=10V, ValueDisplayed=47uF
C20 C21: library part CMP-0007078-4, "CAP, CERM, 0.1 uF, 50 V, +/- 10%, X7R, AEC-Q200 Grade 1, 0603", Cap_Case=0603, Manufacturer=TDK, Supplier Part Number 1=445-5666-1-ND, TempCo=X7R, Tolerance_%=10%, Value1="0.0296 ohm", Value2=50V, ValueDisplayed=0.1uF
C22: library part CMP-0860833-1, "CAP, CERM, 33 pF, 50 V,+/- 5%, C0G/NP0, AEC-Q200 Grade 1, 0402", Cap_Case=0402, Manufacturer=MuRata, TempCo=C0G/NP0, Tolerance_%=5%, Value2=50V, ValueDisplayed=33pF
C23: library part CMP-0860832-1, "CAP, CERM, 47 pF, 50 V,+/- 5%, C0G/NP0, AEC-Q200 Grade 1, 0402", Cap_Case=0402, Manufacturer=TDK, TempCo=C0G/NP0, Tolerance_%=5%, Value2=50V, ValueDisplayed=47pF
C24: library part CMP-0006323-2, "CAP, CERM, 6800 pF, 50 V, +/- 10%, X7R, AEC-Q200 Grade 1, 0402", Cap_Case=0402, Manufacturer=TDK, Supplier Part Number 1=445-6892-1-ND, TempCo=X7R, Tolerance_%=10%, Value1="0.391597 ohm", Value2=50V, ValueDisplayed=6800pF
D1: library part CMP-0028894-3, "Diode, Schottky, 100 V, 0.2 A, SOD-523", Manufacturer=STMicroelectronics, Value1=0.2A, Value2=1V
FID1 FID2 FID3 FID4 FID5 FID6: library part CMP-0077181-1, "Fiducial mark.  There is nothing to buy or mount.", Manufacturer=N/A
J1 J3: library part CMP-0055486-1, "TERM BLOCK 2POS 5mm, TH", Manufacturer="Phoenix Contact", PartNumber=1729018, Supplier Part Number 1=651-1729018
J2: library part CMP-0075454-1, "Header, 100mil, 11x1, Gold, TH", Color=Black, Current_A=6.3A, Manufacturer=Samtec, Supplier Part Number 1=SAM1029-11-ND, Voltage_V=550V
J4: library part CMP-0055486-1, "TERM BLOCK 2POS 5mm, TH", Manufacturer="Phoenix Contact", Supplier Part Number 1=651-1729018
L1: library part CMP-0064168-1, "Inductor, Shielded, 1 uH, 7.2 A, 0.012 ohm, SMD", Manufacturer="Wurth Elektronik", Value1="0.012 ohm", Value2=7.2A, ValueDisplayed=1uH
L2: library part CMP-0094039-1, "Common Mode Choke Power 700Ω 4A -40 to 125°C Wire Wound Surface Mount T/R", Digikey Part Number=240-2978-1-ND, Impedance At Frequency="700Ω @ 100MHz", Manufacturer=Laird, Mouser Part Number=739-CM7060P701R-10, Operating Temperature Range="-40°C to +125°C"
L3: library part CMP-0093175-1, "Shielded Power Inductors 3.3uH 20% tol, 6.5mOhm 16.6A", Manufacturer=Coilcraft, Operating Temperature Range=to, Self Resonant Frequency=24MHz, Test Frequency=1MHz, Tolerance_%=20%
L4: library part CMP-0097455-1, "Shielded Power Inductors 3.3uH 22A 5.7mOhm", Manufacturer=Coilcraft, Operating Temperature Range=to, Self Resonant Frequency=21MHz, Test Frequency=1MHz, Tolerance_%=20%
Logo1: library part CMP-0074844-1
Logo2: library part CMP-0074838-1, "Texas Instrument Corporate Signature"
Logo3: library part CMP-0074847-1, "FCC_disclaimer"
Logo4: library part CMP-0074769-1
LOGO5: library part CMP-0074837-2, "IEC 61010-1 Hot Surface Warning", Manufacturer="Texas Instruments"
LOGO6: library part CMP-0074835-1, "IEC 61010-1 High Voltage Warning"
MH1 MH2 MH3 MH4: library part CMP-0078424-2, "PCB Mounting Hole, No Pad", Manufacturer=Any, PartNumber=N/A
NT1: library part CMP-0078142-6, "Single point connection between nets.", Manufacturer=N/A
R1: library part CMP-0020616-3, "RES, 0, 5%, 0.125 W, AEC-Q200 Grade 0, 0805", Manufacturer=Panasonic, Power_W=125mW, Supplier Part Number 1=P0.0ACT-ND, TempCo="600 ppm/C", Tolerance_%=5%, Value2=0.125W, Value_Code=0000, ValueDisplayed=0
R2: library part CMP-0021990-4, "RES, 100 k, 1%, 0.1 W, AEC-Q200 Grade 0, 0603", Manufacturer=Vishay-Dale, Power_W=100mW, Supplier Part Number 1=541-100KHCT-ND, TempCo="100 ppm/C", Tolerance_%=1%, Value2=0.1W, Value_Code=100k
R3 R8: library part CMP-0026753-1, "RES, 100 k, 1%, 0.063 W, AEC-Q200 Grade 0, 0402", Manufacturer="Stackpole Electronics Inc", Power_W=63mW, Supplier Part Number 1=RMCF0402FT100KCT-ND, TempCo="100 ppm/C", Tolerance_%=1%, Value2=0.063W, Value_Code=100k
R4 R5: library part CMP-0081856-1, "RES, 0, 0%, 0.2 W, AEC-Q200 Grade 0, 0402", Manufacturer=Vishay-Dale, Power_W=200mW, Supplier Part Number 1=541-0.0YBTR-ND, Tolerance_%=0%, Value2=0.2W, Value_Code=0
R6: library part CMP-0090651-1, "5 mOhms ±1% 1W Chip Resistor Wide 0805 (2012 Metric), 0508 Automotive AEC-Q200, Current Sense Metal Foil", Digikey Part Number=408-1595-1-ND, Manufacturer=Susumu, Mouser Part Number=754-KRL2012EMR005FT5, Operating Temperature Range="-55°C to +155°C", Power_W=1W, TempCo=50ppm/°C, Tolerance_%=1%
R7: library part CMP-0026067-3, "RES, 19.1 k, 1%, 0.063 W, AEC-Q200 Grade 0, 0402", Manufacturer=Vishay-Dale, Power_W=63mW, Supplier Part Number 1=541-19.1KLCT-ND, TempCo="100 ppm/C", Tolerance_%=1%, Value2=0.063W, Value_Code=19k1, ValueDisplayed=19.1k
R9: library part CMP-0022302-4, "RES, 2.00, 1%, 0.1 W, AEC-Q200 Grade 0, 0603", Manufacturer=Vishay-Dale, Power_W=100mW, Supplier Part Number 1=541-2.00HHCT-ND, TempCo="100 ppm/C", Tolerance_%=1%, Value2=0.1W, Value_Code=2R00, ValueDisplayed=2.00
R10: library part CMP-0025697-4, "RES, 0, 5%, 0.1 W, AEC-Q200 Grade 0, 0603", Manufacturer=Vishay-Dale, Power_W=100mW, Supplier Part Number 1=541-0.0GCT-ND, TempCo="200 ppm/C", Tolerance_%=5%, Value2=0.1W, Value_Code=0000, ValueDisplayed=0
R11 R12: library part CMP-0026404-2, "RES, 49.9, 1%, 0.063 W, AEC-Q200 Grade 0, 0402", Manufacturer=Vishay-Dale, Power_W=63mW, Supplier Part Number 1=541-49.9LCT-ND, TempCo="100 ppm/C", Tolerance_%=1%, Value2=0.063W, Value_Code=49R9, ValueDisplayed=49.9
R13: library part CMP-0026449-2, "RES, 54.9 k, 1%, 0.063 W, AEC-Q200 Grade 0, 0402", Manufacturer=Vishay-Dale, Power_W=63mW, Supplier Part Number 1=541-54.9KLCT-ND, TempCo="100 ppm/C", Tolerance_%=1%, Value2=0.063W, Value_Code=54k9, ValueDisplayed=54.9k
R14: library part CMP-0026468-2, "RES, 5.76 k, 1%, 0.063 W, AEC-Q200 Grade 0, 0402", Manufacturer=Vishay-Dale, Power_W=63mW, Supplier Part Number 1=541-5.76KLCT-ND, TempCo="100 ppm/C", Tolerance_%=1%, Value2=0.063W, Value_Code=5k76, ValueDisplayed=5.76k
R15: library part CMP-0025950-3, "RES, 100 k, 1%, 0.063 W, AEC-Q200 Grade 0, 0402", Manufacturer=Vishay-Dale, Power_W=63mW, Supplier Part Number 1=541-100KLCT-ND, TempCo="100 ppm/C", Tolerance_%=1%, Value2=0.063W, Value_Code=100k
R16: library part CMP-0026284-2, "RES, 30.1 k, 1%, 0.063 W, AEC-Q200 Grade 0, 0402", Manufacturer=Vishay-Dale, Power_W=63mW, Supplier Part Number 1=541-30.1KLCT-ND, TempCo="100 ppm/C", Tolerance_%=1%, Value2=0.063W, Value_Code=30k1, ValueDisplayed=30.1k
R17: library part CMP-0026196-2, "RES, 24.9 k, 1%, 0.063 W, AEC-Q200 Grade 0, 0402", Manufacturer=Vishay-Dale, Power_W=63mW, Supplier Part Number 1=541-24.9KLCT-ND, TempCo="100 ppm/C", Tolerance_%=1%, Value2=0.063W, Value_Code=24k9, ValueDisplayed=24.9k
R18: library part CMP-0026068-3, "RES, 19.6 k, 1%, 0.063 W, AEC-Q200 Grade 0, 0402", Manufacturer=Vishay-Dale, Power_W=63mW, Supplier Part Number 1=541-19.6KLCT-ND, TempCo="100 ppm/C", Tolerance_%=1%, Value2=0.063W, Value_Code=19k6, ValueDisplayed=19.6k
R19: library part CMP-0026822-3, "RES, 0, 5%, 0.063 W, AEC-Q200 Grade 0, 0402", Manufacturer=Vishay-Dale, Power_W=63mW, Supplier Part Number 1=541-0.0JCT-ND, TempCo="200 ppm/C", Tolerance_%=5%, Value2=0.063W, Value_Code=0000, ValueDisplayed=0
TP1 TP2 TP3 TP4 TP5 TP6: library part CMP-0055162-1, "Test Point, Miniature, SMT", Manufacturer=Keystone, Supplier Part Number 1=36-5019TR-ND
U1: library part CMP-0096026-3, "80-V, 8-A Synchronous DC/DC Buck Converter With Ultra-Low IQ, VQFN29", Manufacturer="Texas Instruments", Max Supply Voltage=80V, Min Supply Voltage=4.5V, Operating Temperature Range="-40°C to +150°C", Output Voltage=0.8-55V, Switching Frequency=0.2-2.2MHz
ZZ1: library part CMP-0077236-1
ZZ2: library part CMP-0077237-1
ZZ3: library part CMP-0077238-1

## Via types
v1: diameter 22, hole 10, Top Layer to Bottom Layer, tented both sides, 364 vias
v2: diameter 19.68, hole 7.87, Top Layer to Bottom Layer, 12 vias
v3: diameter 22, hole 10, Top Layer to Bottom Layer, 5 vias

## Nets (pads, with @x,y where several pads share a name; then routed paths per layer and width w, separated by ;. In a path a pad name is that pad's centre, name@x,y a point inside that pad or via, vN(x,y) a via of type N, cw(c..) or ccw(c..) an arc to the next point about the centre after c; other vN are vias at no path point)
AGND: C6.1 C23.2 C24.2 NT1.2 R18.1 U1.17
BIAS: J2.11 R5.2 R10.2 U1.6 | length 631.6
  Top Layer w9: R10.2@1579.69,1332.13 1581.65,1332.13 R10.2@1592.44,1342.92 ; R10.2@1589.53,1332.13 1632.31,1332.13 1660.97,1360.79 U1.6@1695.83,1360.79
  Top Layer w10: J2.11@1330.81,972.34 1330.81,1058.08 1348.13,1075.4 1348.13,1112.8 1380.68,1145.34 1430.66,1145.34 1580.74,1295.43 1580.74,1323.34 R10.2@1589.53,1332.13
COMP: C23.1 R8.1 R14.2 R19.2 U1.15 | length 230.4
  Top Layer w10: U1.15@1869.06,1295.83 1869.13,1295.75 1869.13,1275.14 1876.57,1267.71 v1(1876.57,1265) 1876.23,1264.66 1876.23,1220.37 R14.2@1875.89,1220.03 ; R14.2@1875,1219.69 1875,1217.72 1879.84,1212.87 1881.81,1212.87 1891.57,1203.11 1892.06,1203.11 1892.33,1202.84 1905.47,1202.84 C23.1@1910.32,1198 ; C23.1@1907.77,1202.84 C23.1@1910.27,1200.34
  Bottom Layer w10: R19.2@1875.31,1200 1875.94,1200.63 1875.94,1264.37 v1(1876.57,1265) R8.1@1876.57,1301.73
CONFIG: R16.2 U1.13 | length 76.7
  Top Layer w10: R16.2@1822,1225.34 1833.39,1236.73 1833.39,1273.35 1829.76,1276.97 1829.76,1295.75 U1.13@1829.68,1295.83
EMIGND: C2.2 C3.2 J1.2 L2.3 TP2.1 | length 201.9
  Top Layer w24: v3(202,1210) J1.2@202.81,1411.92
EN/UVLO: J2.8 R2.1 R7.2 U1.9 | length 541.6
  Top Layer w10: v1(1706.22,1259.34) 1731.26,1284.38 U1.9@1731.26,1295.83
  Signal Layer 2 w8: J2.8@1630.81,972.34 1668.5,1010.03 1668.5,1221.63 v1(1706.22,1259.34)
  Bottom Layer w10: J2.8@1630.81,972.34 1630.81,1071.59 1627.06,1075.34 1696.15,1075.34 R7.2@1698.17,1077.37
FBA: J2.5 R15.1 R17.1 R18.2 U1.16 | length 519.5
  Top Layer w8: U1.16@1889.31,1285.3 1906.11,1268.5 1906.11,1254.14 1912.5,1247.74 1911.41,1246.65 1911.41,1229.81 v1@1912.5,1228.72 ; R15.1@1895.57,1074.79 1917.24,1074.79 1930.81,1061.21 J2.5@1930.81,972.34
  Signal Layer 2 w8: v1@1912.5,1228.72 1930.81,1210.4 J2.5@1930.81,972.34
  Bottom Layer w10: v1@1912.5,1228.72 1914.8,1231.01 1933.91,1231.01 1958.21,1255.32 R17.1@1958.21,1257.29
  other v1: 1912,1228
